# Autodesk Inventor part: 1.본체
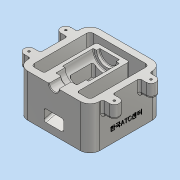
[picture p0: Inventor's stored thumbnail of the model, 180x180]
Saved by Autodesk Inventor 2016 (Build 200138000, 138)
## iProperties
Created: 2018-01
Part Number: 1.본체
Material: 알루미늄 6061
Document SubType Name: Modeling
Designer: Administrator
Density: 2.7 g/cm^3
Appearance: 알루미늄 - 평지
Mass: 995.298 g
Surface Area: 835.166 cm^2
Volume: 368.629 cm^3
Author: Administrator
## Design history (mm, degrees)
sketch "스케치1"
  geometry: L1 (-55, -55)-(55, -55); L2 (55, -55)-(55, 55); L3 (55, 55)-(-55, 55); L4 (-55, 55)-(-55, -55); L5 (-55, -55)-(55, 55); L6 (55, -55)-(-55, 55); 1 further point
  constraints: 12 end point, 2 midpoint, 2 parallel, 1 horizontal, 1 perpendicular
  dimensions: "d0" = 110 distance of L3.end L2.end; "d1" = 110 distance of L2.end L1.end
extrude "돌출1" new body sketch "스케치1" distance "d2" = 65; taper "d3" = 0 deg
sketch "스케치2"
  geometry: L1 (-55, -55)-(55, -55) reference; L2 (55, -55)-(55, 55) reference; L3 (55, 55)-(-55, 55) reference; L4 (-55, 55)-(-55, -55) reference; L5 (55, 35.5)-(65, 35.5); L6 (65, 35.5)-(65, 20.5); L7 (65, 20.5)-(55, 20.5); L8 (55, 20.5)-(55, 35.5); A1 r 7.5 centre (65, 28) between (65, 20.5) and (65, 35.5); 1 further point
  constraints: 8 end point, 2 parallel, 2 point on circle, 1 centre point, 1 horizontal, 1 midpoint, 1 perpendicular, 1 point on line
  dimensions: "d5" = 7.5 radius of A1; "d6" = 10 distance of L6.end L7.end; "d70" = 27 distance from line of A1.centre L3
extrude "돌출2" join sketch "스케치2" distance "d7" = 20; taper "d8" = 0 deg
sketch "스케치3"
  geometry: L1 (-45, 45)-(45, 45); L2 (45, 45)-(45, -45); L3 (45, -45)-(-45, -45); L4 (-45, -45)-(-45, 45); L5 (-45, 45)-(45, -45); L6 (45, 45)-(-45, -45); 1 further point
  constraints: 12 end point, 2 midpoint, 2 parallel, 1 horizontal, 1 perpendicular
  dimensions: "d9" = 90 distance of L2.end L3.end; "d10" = 90 distance of L1.end L2.end
extrude "돌출3" cut sketch "스케치3" stored distance "d11" = 20; taper "d12" = 0 deg
sketch "스케치4"
  geometry: L1 (-55, -55)-(55, -55) reference; L2 (55, 55)-(-55, 55) reference; L3 (-25, 35)-(25, 35); L4 (25, 35)-(25, -55); L5 (25, -55)-(-25, -55); L6 (-25, -55)-(-25, 35); 2 further points
  constraints: 8 end point, 2 parallel, 1 horizontal, 1 midpoint, 1 perpendicular, 1 point on line, 1 vertical alignment
  dimensions: "d13" = 50 distance between parallel lines of L4 L6; "d14" = 20 distance between parallel lines of L2 L3
extrude "돌출4" join sketch "스케치4" distance "d15" = 65; taper "d16" = 0 deg
sketch "스케치5"
  geometry: L1 (-55, 0)-(-55, 65) reference; L2 (-55, 65)-(-55, 57.5); L3 (-55, 57.5)-(-36, 57.5); L4 (-36, 57.5)-(-36, 49); L5 (-36, 49)-(-22, 49); L6 (-22, 49)-(-22, 45); L7 (-22, 45)-(25, 45); L8 (55, 65)-(35.5, 65) reference; L9 (-35.5, 65)-(-55, 65) reference; L10 (-55, 65)-(30, 65); L11 (-45, 65)-(45, 65) reference; L12 (25, 45)-(25, 50); L13 (25, 50)-(30, 50); L14 (30, 50)-(30, 65); 1 further point
  constraints: 20 end point, 6 perpendicular, 2 point on line, 1 collinear, 1 horizontal, 1 vertical
  dimensions: "d17" = 19 distance of L2.end L3.end; "d18" = 14 distance of L4.end L5.end; "d19" = 47 distance of L6.end L7.end; "d20" = 5 distance of L12.end L13.end; "d21" = 15 diameter of L3 L10; "d22" = 32 diameter of L5 L10; "d23" = 40 diameter of L7 L10; "d25" = 15 distance from line of L10.end L13
revolve "회전1" sketch "스케치5" stored, may be unused: angle "d26" = 90 deg
sketch "스케치6"
  geometry: L1 (35, 0)-(35, 30); L2 (35, 65)-(35, 0) reference; L3 (35, 30)-(-45, 8.564); L4 (-45, 8.564)-(-45, 0); L5 (45, 0)-(-45, 0) reference; L6 (-45, 0)-(35, 0); L7 (-22, 45)-(25, 45) reference; L8 (-17, 45)-(20, 45); L9 (-55, 0)-(-55, 65) reference; L10 (-55, 11.061)-(-55, 29.061); L11 (-55, 29.061)-(-17, 39.243); L12 (-17, 39.243)-(-17, 45); L13 (-45, 65)-(-45, 0) reference; L14 (-55, 11.061)-(20, 31.157); L15 (20, 31.157)-(20, 45); 3 further points
  constraints: 20 end point, 6 point on line, 4 parallel, 2 midpoint, 1 coincident, 1 collinear
  dimensions: "d27" = 30 distance of L1.start L1.end; "d28" = 105 deg angle of L4 L3; "d29" = 5 distance between parallel lines of L3 L14; "d30" = 37 distance of L8.start L8.end; "d31" = 75 deg angle of L9 L11; "d32" = 18 distance of L10.start L10.end; "d54" = 10 distance between parallel lines of L9 L4
extrude "돌출5" cut sketch "스케치6" stored distance "d33" = 30; taper "d34" = 0 deg
extrude "돌출6" cut sketch "스케치6" stored distance "d35" = 50; taper "d36" = 0 deg
node "작업 평면1"
sketch "스케치7"
  geometry: L1 (-15, -17)-(15, -17); L2 (15, -17)-(15, 20); L3 (15, 20)-(-15, 20); L4 (-15, 20)-(-15, -17); L5 (0, 20)-(0, -17) reference; L6 (-15, -17)-(15, 20); L7 (15, -17)-(-15, 20); 2 further points
  constraints: 12 end point, 3 midpoint, 2 parallel, 1 horizontal, 1 perpendicular
  dimensions: "d38" = 30 distance of L3.end L2.end; "d39" = 37 distance of L2.end L1.end
extrude "돌출7" cut sketch "스케치7" stored distance "d40" = 50; taper "d41" = 0 deg
fillet "모깎기1" dims "d42" = 1
fillet "모깎기2" dims "d43" = 3
fillet "모깎기3" dims "d44" = 15
fillet "모깎기4" dims "d45" = 3
fillet "모깎기5" dims "d46" = 3
fillet "모깎기6" dims "d48" = 5
chamfer "모따기1" distance "d50" = 1; stored, may be unused: second distance "d51" = 2, angle "d52" = 45 deg
fillet "모깎기7" dims "d53" = 3
hole "구멍1" diameter "d59" = 3.242; stored, may be unused: countersink angle "d63" = 90 deg, drill point angle "d65" = 118 deg; dims "d57" = 10, "d58" = 10, "d60" = 9, "d61" = 4, "d62" = 2, "d64" = 11
fillet "모깎기10" dims "d66" = 3
sketch "스케치8"
  geometry: L1 (0, 0)-(0, 80) reference; 3 further points
  constraints: 1 horizontal alignment, 1 midpoint, 1 other
  dimensions: "d67" = 20 distance of point (0, 40) point (-20, 40)
feature "엠보싱1" sketch "스케치8" dims "d0" = 110, "d1" = 110, "d68" = 0.5, "d69" = 0
node "솔리드1"
mirror "대칭1"
mirror "대칭2"
mirror "대칭3"
mirror "대칭4"
